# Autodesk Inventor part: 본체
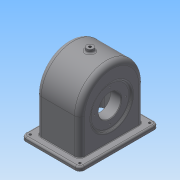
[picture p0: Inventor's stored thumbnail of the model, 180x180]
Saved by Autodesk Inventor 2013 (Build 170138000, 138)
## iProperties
Created: 2016-01
Part Number: 본체
Material: 일반
Document SubType Name: Modeling
Designer: Administrator
Density: 1 g/cm^3
Author: Administrator
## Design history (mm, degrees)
sketch "스케치1"
  geometry: L1 (-44, 70)-(44, 70); L2 (52, 62)-(52, -62); L3 (44, -70)-(-44, -70); L4 (-52, -62)-(-52, 62); A1 r 8 centre (-44, 62) between (-44, 70) and (-52, 62); A2 r 8 centre (-44, -62) between (-52, -62) and (-44, -70); A3 r 8 centre (44, -62) between (44, -70) and (52, -62); A4 r 8 centre (44, 62) between (52, 62) and (44, 70); 3 further points
  constraints: 8 end point, 8 point on circle, 8 tangent, 4 centre point, 3 equal radius, 2 midpoint, 2 parallel, 1 horizontal, 1 horizontal alignment, 1 perpendicular, 1 vertical alignment
  dimensions: "d0" = 140 distance between parallel lines of L3 L1; "d2" = 104 distance between parallel lines of L2 L4; "d3" = 8 radius of A1
extrude "돌출1" new body sketch "스케치1" distance "d4" = 7; taper "d5" = 0 deg
sketch "스케치2"
  geometry: L1 (-62, 0)-(62, 0) reference; L2 (-70, 0)-(-70, 7) reference; L3 (70, 0)-(70, 7) reference; L4 (62, 7)-(-62, 7) reference; L5 (-57, 70)-(-57, 7); L6 (57, 70)-(57, 7); A1 r 57 centre (0, 70) between (57, 70) and (-57, 70); 2 further points
  constraints: 4 end point, 2 perpendicular, 2 point on circle, 2 point on line, 2 tangent, 1 centre point, 1 midpoint, 1 vertical alignment
  dimensions: "d6" = 114 diameter of A1; "d10" = 127 dimension on A1 L1
extrude "돌출2" join sketch "스케치2" stored distance "d11" = 77; taper "d12" = 0 deg
node "작업 평면3"
  node "작업 평면2"
sketch "스케치3"
  geometry: L1 (57, 70)-(57, 7) reference; L2 (-57, 7)-(57, 7) reference; L3 (-57, 7)-(-57, 70) reference; L4 (51, 70)-(51, 0); L5 (-51, 0)-(-51, 70); L6 (-62, 0)-(62, 0) reference; A1 r 57 centre (0, 70) between (57, 70) and (-57, 70) reference; A2 r 51 centre (0, 70) between (51, 70) and (-51, 70); 1 further point
  constraints: 4 end point, 2 point on circle, 2 point on line, 1 centre point, 1 other
  dimensions: "d16" = 6 distance between parallel lines of L5 L3; "d17" = 51 radius of A2
extrude "돌출3" cut sketch "스케치3" distance "d18" = 67; taper "d19" = 0 deg
sketch "스케치4"
  geometry: L1 (33.5, 0)-(-33.5, 0) reference; L2 (-38.5, 70)-(-38.5, 7) reference; L3 (38.5, 7)-(38.5, 70) reference; L4 (38.5, 70)-(38.5, 127) reference; L5 (-52.804, 60)-(49.974, 60); L6 (-33.5, 70)-(-33.5, 121) reference; L7 (-33.5, 0)-(-33.5, 70) reference; L8 (-35.5, 94.899)-(-35.5, 60); L9 (-33.5, 99.747)-(-19.5, 88); L10 (-19.5, 88)-(-19.5, 60); L11 (-35.5, 60)-(-19.5, 60); L12 (-35.5, 94.899)-(-41.279, 99.747); L13 (-33.5, 99.747)-(-41.279, 99.747); L14 (-38.5, 127)-(-38.5, 70) reference; 1 further point
  constraints: 14 end point, 3 perpendicular, 3 point on line, 2 parallel, 1 collinear
  dimensions: "d20" = 60 distance between parallel lines of L1 L5; "d21" = 5 distance between parallel lines of L9 L12; "d22" = 16 distance between parallel lines of L10 L8; "d23" = 56 diameter of L9.end L5; "d24" = 3 distance between parallel lines of L8 L14; "d25" = 50 deg angle of L10 L9
revolve "회전1" sketch "스케치4" stored, may be unused: angle "d26" = 90 deg
sketch "스케치5"
  geometry: C1 r 31 at (60, 0); A1 r 57 centre (70, 0) between (70, -57) and (70, 57) reference; 1 further point
  constraints: 1 centre point, 1 horizontal alignment
  dimensions: "d27" = 62 diameter of C1; "d29" = 60 distance of C1.centre point (0, 0)
extrude "돌출4" join sketch "스케치5" distance "d30" = 10; taper "d31" = 0 deg
hole "구멍1" diameter "d34" = 40; stored, may be unused: countersink angle "d38" = 90 deg, drill point angle "d40" = 118 deg; dims "d32" = 10, "d33" = 10, "d35" = 6, "d36" = 4, "d37" = 2, "d39" = 8
sketch "스케치6" dims "d41" = 56
  geometry: C1 r 20 at (0, 0) reference; 3 further points
  constraints: 2 horizontal alignment, 1 coincident, 2 other
hole "구멍2" sketch "스케치6" at (-28, 0) diameter "d43" = 2.459; stored, may be unused: countersink angle "d47" = 90 deg, drill point angle "d49" = 118 deg; dims "d44" = 7, "d45" = 4, "d46" = 2, "d48" = 9
sketch "스케치7" dims "d53" = 48
  geometry: C1 r 20 at (0, 0) reference; 3 further points
  constraints: 2 horizontal alignment, 1 coincident, 2 other
hole "구멍3" sketch "스케치7" at (24, 0) diameter "d55" = 2.459; stored, may be unused: countersink angle "d59" = 90 deg, drill point angle "d61" = 118 deg; dims "d56" = 6, "d57" = 4, "d58" = 2, "d60" = 8
node "작업 평면5"
  node "작업 평면4"
sketch "스케치8"
  geometry: C1 r 6 at (38.5, 0); 1 further point
  constraints: 1 centre point, 1 coincident
  dimensions: "d66" = 12 diameter of C1
extrude "돌출5" join sketch "스케치8" distance "d68" = 10; taper "d69" = 0 deg
hole "구멍4" diameter "d72" = 4.459; stored, may be unused: countersink angle "d76" = 90 deg, drill point angle "d78" = 118 deg; dims "d70" = 10, "d71" = 10, "d73" = 30, "d74" = 4, "d75" = 2, "d77" = 8
fillet "모깎기1" dims "d79" = 3
hole "구멍5" diameter "d82" = 4; stored, may be unused: countersink angle "d86" = 90 deg, drill point angle "d88" = 118 deg; dims "d80" = 10, "d81" = 10, "d83" = 8, "d84" = 4, "d85" = 2, "d87" = 8
hole "구멍6" diameter "d91" = 4; stored, may be unused: countersink angle "d95" = 90 deg, drill point angle "d97" = 118 deg; dims "d89" = 10, "d90" = 10, "d92" = 8, "d93" = 4, "d94" = 2, "d96" = 8
hole "구멍7" diameter "d100" = 4; stored, may be unused: countersink angle "d104" = 90 deg, drill point angle "d106" = 118 deg; dims "d98" = 10, "d99" = 10, "d101" = 8, "d102" = 4, "d103" = 2, "d105" = 8
hole "구멍8" diameter "d109" = 4; stored, may be unused: countersink angle "d113" = 90 deg, drill point angle "d115" = 118 deg; dims "d107" = 10, "d108" = 10, "d110" = 8, "d111" = 4, "d112" = 2, "d114" = 8
fillet "모깎기2" dims "d116" = 9
fillet "모깎기3" dims "d117" = 9
fillet "모깎기4" dims "d118" = 3
feature "면 이동1"
feature "면 이동2"
feature "면 이동3" dims "d119" = 3
sketch "스케치9"
  geometry: L1 (-112.375, 55.631)-(-12.239, 55.631); L2 (-12.239, 55.631)-(-12.239, -42.465); L3 (-12.239, -42.465)-(-112.375, -42.465); L4 (-112.375, -42.465)-(-112.375, 55.631); 1 further point
  constraints: 8 end point, 2 parallel, 1 horizontal, 1 perpendicular
extrude "돌출6" cut sketch "스케치9" distance "d120" = 10; taper "d121" = 0 deg
fillet "모깎기5" dims "d122" = 3
fillet "모깎기6" dims "d123" = 1
fillet "모깎기7" dims "d124" = 3
chamfer "모따기1" distance "d125" = 1; stored, may be unused: second distance "d126" = 2, angle "d127" = 45 deg
chamfer "모따기2" distance "d128" = 1; stored, may be unused: second distance "d129" = 2, angle "d130" = 45 deg
fillet "모깎기8" dims "d131" = 3
sketch "스케치10"
  geometry: L1 (54.387, 23.094)-(4.613, 23.094); L2 (4.613, 23.094)-(4.613, 56.906); L3 (4.613, 56.906)-(54.387, 56.906); L4 (54.387, 56.906)-(54.387, 23.094); L5 (-14.5, 70)-(73.5, 70) reference; 5 further points
  constraints: 3 midpoint, 2 vertical alignment, 1 horizontal alignment, 2 other
  dimensions: "d132" = 30 distance from line of L5 point (29.5, 40)
feature "엠보싱1" sketch "스케치10" dims "d0" = 140, "d2" = 104, "d3" = 8, "d133" = 0.5, "d134" = 0
node "솔리드1"
pattern_circular "원형 패턴1" dims angle "d51" = 360 deg
pattern_circular "원형 패턴2" dims angle "d63" = 360 deg
node "작업 평면1"
node "투영된 루프1"
other parameters: "d13" = 38.5, "d14" = -6, "d15" = 1, "d65" = 6
